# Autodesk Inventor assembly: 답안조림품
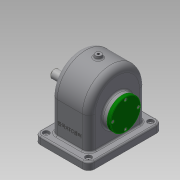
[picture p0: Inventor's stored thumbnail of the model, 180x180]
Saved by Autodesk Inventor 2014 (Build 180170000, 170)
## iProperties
Created: 2016-10
Part Number: 답안조림품
Document SubType Name: Assembly
Designer: q
Author: q
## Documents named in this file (15)
- C:\Users\q\Desktop\461008V1016\답안조림품.iam
- C:\Users\q\Desktop\461008V1016\베어링 6203.ipt
- C:\Users\q\Desktop\461008V1016\축.ipt
- C:\Users\q\Desktop\461008V1016\스퍼기어.ipt
- C:\Users\q\Desktop\461008V1016\키 - 6 x 6 x 22.ipt
- C:\Users\q\Desktop\461008V1016\키 - 5 x 5 x 18.ipt
- C:\Users\q\Desktop\461008V1016\부시.ipt
- C:\Users\q\Desktop\461008V1016\V-벨트풀리.ipt
- C:\Users\q\Desktop\461008V1016\멈춤나사 - M4x10.ipt
- C:\Users\q\Desktop\461008V1016\본체.ipt
- C:\Users\q\Desktop\461008V1016\볼트 M3 x 8.ipt
- C:\Users\q\Desktop\461008V1016\뒤커버.ipt
- C:\Users\q\Desktop\461008V1016\볼트 M3 x 10.ipt
- C:\Users\q\Desktop\461008V1016\앞커버.ipt
- C:\Users\q\Desktop\461008V1016\오일씰 28 40 8.ipt
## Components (9 placed, 3 different names)
1. V-벨트풀리:1
2. ISO 4762 M3 x 8:1
3. ISO 4762 M3 x 8:2
4. ISO 4762 M3 x 8:3
5. ISO 4762 M3 x 8:4
6. ISO 4762 M3 x 10:1
7. ISO 4762 M3 x 10:2
8. ISO 4762 M3 x 10:3
9. ISO 4762 M3 x 10:4
